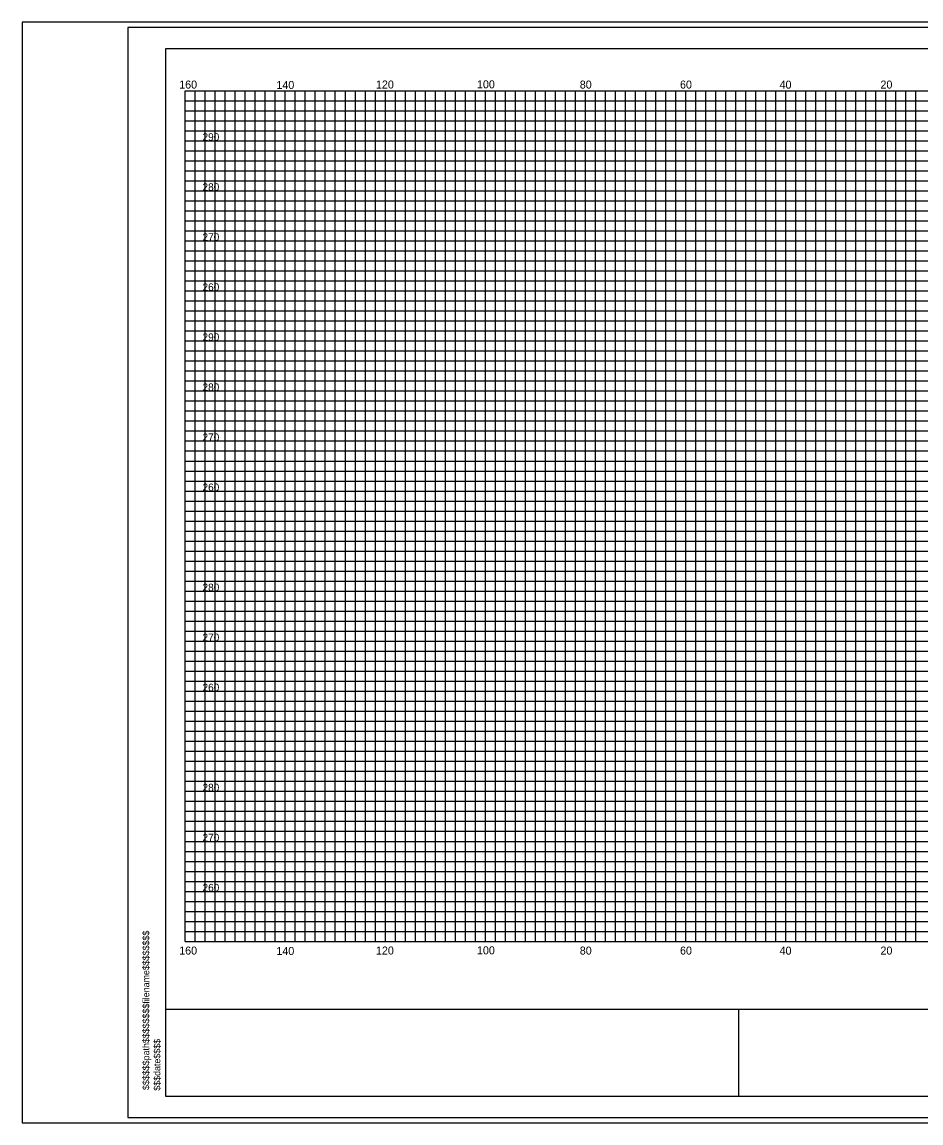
# Model space of a CAD drawing. Extents: x 967 to 1326, y 964 to 3704.
# Drawn here: x 967.4 to 1147, y 1803.7 to 2023.7 of the extents above; entities that cross this region are included whole.
import ezdxf

# ---------------------------------------------------------------- set-up
doc = ezdxf.new("R2010")
doc.units = 0
for name, color, linetype in [('Default', 7, 'Continuous'), ('RD_SHT_Bndy', 7, 'Continuous'), ('RD_SHT_IplotShp', 7, 'Continuous'), ('RD_SHT_MjGrid', 7, 'Continuous'), ('RD_SHT_MnGrid', 7, 'Continuous'), ('RD_SHT_TX', 7, 'Continuous'), ('RD_XS_TX_Station', 7, 'Continuous')]:
    doc.layers.add(name, color=color, linetype=linetype)

msp = doc.modelspace()

# ---------------------------------------------------------------- linework, layer by layer
at = {"layer": 'RD_SHT_Bndy'}
for p, q in [((996.11, 1808.98), (996.11, 2018.46)), ((996.11, 2018.46), (1323.89, 2018.46)), ((996.11, 1826.49), (1323.89, 1826.49)), ((1110.59, 1808.98), (1110.59, 1826.56)), ((1323.89, 1808.98), (996.11, 1808.98))]:
    msp.add_line(p, q, dxfattribs=at)
at = {"layer": 'RD_SHT_IplotShp'}
for points in [[(967.41, 1803.72), (1326.28, 1803.72), (1326.28, 2023.72), (967.41, 2023.72)], [(988.52, 1804.84), (1326.28, 1804.84), (1326.28, 2022.6), (988.52, 2022.6)]]:
    msp.add_lwpolyline(points, close=True, dxfattribs=at)
at = {"layer": 'RD_SHT_MjGrid'}
for p, q in [((1000, 2010), (1320, 2010)), ((1000, 1840), (1000, 2010)), ((1010, 1840), (1010, 2010)), ((1020, 1840), (1020, 2010)), ((1030, 1840), (1030, 2010)), ((1040, 1840), (1040, 2010)), ((1050, 1840), (1050, 2010)), ((1060, 1840), (1060, 2010)), ((1070, 1840), (1070, 2010)), ((1080, 1840), (1080, 2010)), ((1090, 1840), (1090, 2010)), ((1100, 1840), (1100, 2010)), ((1110, 1840), (1110, 2010)), ((1120, 1840), (1120, 2010)), ((1130, 1840), (1130, 2010)), ((1140, 1840), (1140, 2010)), ((1000, 2000), (1320, 2000)), ((1000, 1990), (1320, 1990)), ((1000, 1980), (1320, 1980)), ((1000, 1970), (1320, 1970)), ((1000, 1960), (1320, 1960)), ((1000, 1950), (1320, 1950)), ((1000, 1940), (1320, 1940)), ((1000, 1930), (1320, 1930)), ((1000, 1920), (1320, 1920)), ((1000, 1910), (1320, 1910)), ((1000, 1900), (1320, 1900)), ((1000, 1890), (1320, 1890)), ((1000, 1880), (1320, 1880)), ((1000, 1870), (1320, 1870)), ((1000, 1860), (1320, 1860)), ((1000, 1850), (1320, 1850)), ((1000, 1840), (1320, 1840))]:
    msp.add_line(p, q, dxfattribs=at)
at = {"layer": 'RD_SHT_MnGrid'}
for p, q in [((1002, 1840), (1002, 2010)), ((1004, 1840), (1004, 2010)), ((1006, 1840), (1006, 2010)), ((1008, 1840), (1008, 2010)), ((1012, 1840), (1012, 2010)), ((1014, 1840), (1014, 2010)), ((1016, 1840), (1016, 2010)), ((1018, 1840), (1018, 2010)), ((1022, 1840), (1022, 2010)), ((1024, 1840), (1024, 2010)), ((1026, 1840), (1026, 2010)), ((1028, 1840), (1028, 2010)), ((1032, 1840), (1032, 2010)), ((1034, 1840), (1034, 2010)), ((1036, 1840), (1036, 2010)), ((1038, 1840), (1038, 2010)), ((1042, 1840), (1042, 2010)), ((1044, 1840), (1044, 2010)), ((1046, 1840), (1046, 2010)), ((1048, 1840), (1048, 2010)), ((1052, 1840), (1052, 2010)), ((1054, 1840), (1054, 2010)), ((1056, 1840), (1056, 2010)), ((1058, 1840), (1058, 2010)), ((1062, 1840), (1062, 2010)), ((1064, 1840), (1064, 2010)), ((1066, 1840), (1066, 2010)), ((1068, 1840), (1068, 2010)), ((1072, 1840), (1072, 2010)), ((1074, 1840), (1074, 2010)), ((1076, 1840), (1076, 2010)), ((1078, 1840), (1078, 2010)), ((1082, 1840), (1082, 2010)), ((1084, 1840), (1084, 2010)), ((1086, 1840), (1086, 2010)), ((1088, 1840), (1088, 2010)), ((1092, 1840), (1092, 2010)), ((1094, 1840), (1094, 2010)), ((1096, 1840), (1096, 2010)), ((1098, 1840), (1098, 2010)), ((1102, 1840), (1102, 2010)), ((1104, 1840), (1104, 2010)), ((1106, 1840), (1106, 2010)), ((1108, 1840), (1108, 2010)), ((1112, 1840), (1112, 2010)), ((1114, 1840), (1114, 2010)), ((1116, 1840), (1116, 2010)), ((1118, 1840), (1118, 2010)), ((1122, 1840), (1122, 2010)), ((1124, 1840), (1124, 2010)), ((1126, 1840), (1126, 2010)), ((1128, 1840), (1128, 2010)), ((1132, 1840), (1132, 2010)), ((1134, 1840), (1134, 2010)), ((1136, 1840), (1136, 2010)), ((1138, 1840), (1138, 2010)), ((1142, 1840), (1142, 2010)), ((1144, 1840), (1144, 2010)), ((1146, 1840), (1146, 2010)), ((1000, 2008), (1320, 2008)), ((1000, 2006), (1320, 2006)), ((1000, 2004), (1320, 2004)), ((1000, 2002), (1320, 2002)), ((1000, 1998), (1320, 1998)), ((1000, 1996), (1320, 1996)), ((1000, 1994), (1320, 1994)), ((1000, 1992), (1320, 1992)), ((1000, 1988), (1320, 1988)), ((1000, 1986), (1320, 1986)), ((1000, 1984), (1320, 1984)), ((1000, 1982), (1320, 1982)), ((1000, 1978), (1320, 1978)), ((1000, 1976), (1320, 1976)), ((1000, 1974), (1320, 1974)), ((1000, 1972), (1320, 1972)), ((1000, 1968), (1320, 1968)), ((1000, 1966), (1320, 1966)), ((1000, 1964), (1320, 1964)), ((1000, 1962), (1320, 1962)), ((1000, 1958), (1320, 1958)), ((1000, 1956), (1320, 1956)), ((1000, 1954), (1320, 1954)), ((1000, 1952), (1320, 1952)), ((1000, 1948), (1320, 1948)), ((1000, 1946), (1320, 1946)), ((1000, 1944), (1320, 1944)), ((1000, 1942), (1320, 1942)), ((1000, 1938), (1320, 1938)), ((1000, 1936), (1320, 1936)), ((1000, 1934), (1320, 1934)), ((1000, 1932), (1320, 1932)), ((1000, 1928), (1320, 1928)), ((1000, 1926), (1320, 1926)), ((1000, 1924), (1320, 1924)), ((1000, 1922), (1320, 1922)), ((1000, 1918), (1320, 1918)), ((1000, 1916), (1320, 1916)), ((1000, 1914), (1320, 1914)), ((1000, 1912), (1320, 1912)), ((1000, 1908), (1320, 1908)), ((1000, 1906), (1320, 1906)), ((1000, 1904), (1320, 1904)), ((1000, 1902), (1320, 1902)), ((1000, 1898), (1320, 1898)), ((1000, 1896), (1320, 1896)), ((1000, 1894), (1320, 1894)), ((1000, 1892), (1320, 1892)), ((1000, 1888), (1320, 1888)), ((1000, 1886), (1320, 1886)), ((1000, 1884), (1320, 1884)), ((1000, 1882), (1320, 1882)), ((1000, 1878), (1320, 1878)), ((1000, 1876), (1320, 1876)), ((1000, 1874), (1320, 1874)), ((1000, 1872), (1320, 1872)), ((1000, 1868), (1320, 1868)), ((1000, 1866), (1320, 1866)), ((1000, 1864), (1320, 1864)), ((1000, 1862), (1320, 1862)), ((1000, 1858), (1320, 1858)), ((1000, 1856), (1320, 1856)), ((1000, 1854), (1320, 1854)), ((1000, 1852), (1320, 1852)), ((1000, 1848), (1320, 1848)), ((1000, 1846), (1320, 1846)), ((1000, 1844), (1320, 1844)), ((1000, 1842), (1320, 1842))]:
    msp.add_line(p, q, dxfattribs=at)
at = {"layer": 'RD_XS_TX_Station'}
msp.add_lwpolyline([(967.41, 1803.72), (1326.28, 1803.72), (1326.28, 2023.72), (967.41, 2023.72)], close=True, dxfattribs=at)

# ---------------------------------------------------------------- texts
at = {"layer": 'Default'}
for s, p in [('290', (1003.47, 2000)), ('280', (1003.47, 1990)), ('270', (1003.47, 1980)), ('260', (1003.47, 1970)), ('290', (1003.47, 1960)), ('280', (1003.47, 1950)), ('270', (1003.47, 1940)), ('260', (1003.47, 1930)), ('280', (1003.47, 1910)), ('270', (1003.47, 1900)), ('260', (1003.47, 1890)), ('280', (1003.47, 1870)), ('270', (1003.47, 1860)), ('260', (1003.47, 1850))]:
    msp.add_text(s, height=1.5, dxfattribs=at).set_placement(p)
for s, p in [('$$$$$$path$$$$$$$$filename$$$$$$$$', (992.83, 1810.31)), ('$$$date$$$$', (995.04, 1810.17))]:
    msp.add_text(s, height=1.3258, rotation=90, dxfattribs=at).set_placement(p)
at = {"layer": 'RD_SHT_TX'}
for s, p in [('160', (998.81, 2010.42)), ('140', (1018.23, 2010.34)), ('120', (1038.12, 2010.43)), ('100', (1058.3, 2010.47)), ('80', (1078.84, 2010.42)), ('60', (1098.86, 2010.42)), ('40', (1118.75, 2010.41)), ('20', (1138.91, 2010.42)), ('160', (998.81, 1837.37)), ('140', (1018.23, 1837.29)), ('120', (1038.12, 1837.38)), ('100', (1058.3, 1837.42)), ('80', (1078.84, 1837.37)), ('60', (1098.86, 1837.37)), ('40', (1118.75, 1837.36)), ('20', (1138.91, 1837.37))]:
    msp.add_text(s, height=1.6, dxfattribs=at).set_placement(p)

doc.saveas('drawing.dxf')
